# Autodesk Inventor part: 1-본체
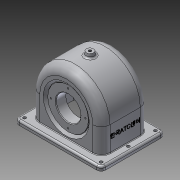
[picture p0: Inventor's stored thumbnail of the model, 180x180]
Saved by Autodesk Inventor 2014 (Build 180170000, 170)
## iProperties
Created: 2015-09
Part Number: 1-본체
Material: 알루미늄 6061
Document SubType Name: Modeling
Designer: Administrator
Density: 2.71 g/cm^3
Appearance: 알루미늄 - 평지
Mass: 809.5 g
Surface Area: 878.329 cm^2
Volume: 298.708 cm^3
Author: Administrator
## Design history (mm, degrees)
sketch "스케치1"
  geometry: L1 (57, 0)-(57, -47); L2 (57, -47)-(-57, -47); L3 (-57, -47)-(-57, 0); L4 (57, 0)-(-57, 0); A1 r 57 centre (0, 0) between (57, 0) and (-57, 0); 1 further point
  constraints: 8 end point, 2 perpendicular, 2 point on circle, 2 tangent, 1 centre point, 1 coincident, 1 vertical
  dimensions: "d3" = 57 radius of A1; "d4" = 104 dimension on A1 L2
extrude "돌출1" new body sketch "스케치1" distance "d5" = 77; taper "d6" = 0 deg
sketch "스케치2"
  geometry: L1 (-13, -13.5)-(127, -13.5); L2 (127, -13.5)-(127, 90.5); L3 (127, 90.5)-(-13, 90.5); L4 (-13, 90.5)-(-13, -13.5); L5 (0, 0)-(0, 77) reference; L6 (114, 0)-(0, 0) reference; 5 further points
  constraints: 8 end point, 4 midpoint, 2 parallel, 1 horizontal, 1 horizontal alignment, 1 perpendicular, 1 vertical alignment
  dimensions: "d7" = 140 distance of L2.end L3.end; "d8" = 104 distance of L3.end L1.start
extrude "돌출2" join sketch "스케치2" distance "d9" = 7; taper "d10" = 0 deg
fillet "모깎기1" dims "d11" = 14
feature "쉘1" dims "d12" = 5, "d103" = 7
sketch "스케치3"
  geometry: C1 r 31 at (0, 0); 1 further point
  constraints: 1 centre point, 1 coincident
  dimensions: "d13" = 62 diameter of C1
extrude "돌출3" join sketch "스케치3" distance "d14" = 10; taper "d15" = 0 deg
sketch "스케치4"
  geometry: L1 (5, 39.747)-(19, 28); L2 (19, 28)-(19, 0); L3 (19, 0)-(5, 0); L4 (5, 0)-(5, 39.747); L5 (5, 0)-(5, 43) reference; 1 further point
  constraints: 8 end point, 2 perpendicular, 1 collinear, 1 point on line, 1 vertical
  dimensions: "d16" = 28 distance of L1.end L2.end; "d17" = 50 deg angle of L2 L1; "d18" = 14 distance of L2.end L3.end
revolve "회전1" sketch "스케치4" stored, may be unused: angle "d19" = 90 deg
sketch "스케치7"
  geometry: L1 (5, 39.747)-(19, 28) reference; L2 (0, 37.416)-(5.263, 33); L3 (0, 0)-(0, 43) reference; L4 (3, 0)-(3, 33); L5 (3, 33)-(5.263, 33); L6 (3, 0)-(0, 0)
  constraints: 8 end point, 2 parallel, 1 horizontal, 1 perpendicular, 1 point on line
  dimensions: "d21" = 5 distance between parallel lines of L2 L1; "d22" = 3 distance between parallel lines of L4 L3; "d23" = 33 distance of L4.start L4.end
revolve "회전2" sketch "스케치7" stored, may be unused: angle "d25" = 90 deg
hole "구멍1" diameter "d28" = 40; stored, may be unused: countersink angle "d32" = 90 deg, drill point angle "d34" = 0 deg; dims "d26" = 10, "d27" = 10, "d29" = 6, "d30" = 4, "d31" = 2, "d33" = 8
node "작업 평면1"
sketch "스케치8"
  geometry: L1 (140, 104)-(140, 0) reference; L2 (0, 104)-(140, 104) reference; C1 r 6 at (70, 52); 2 further points
  constraints: 1 centre point, 1 horizontal alignment, 1 midpoint, 1 vertical alignment
  dimensions: "d37" = 12 diameter of C1
extrude "돌출4" join sketch "스케치8" stored distance "d38" = 5; taper "d39" = 10 deg
fillet "모깎기2" dims "d40" = 7
fillet "모깎기3" dims "d41" = 3
sketch "스케치9"
  geometry: L1 (0, 0)-(0, 28)
  constraints: 2 end point, 1 vertical
  dimensions: "d42" = 28 distance of L1.start L1.end
hole "구멍2" sketch "스케치9" at (0, 28) diameter "d43" = 2.459; stored, may be unused: countersink angle "d47" = 90 deg, drill point angle "d49" = 118 deg; dims "d44" = 7, "d45" = 4, "d46" = 2, "d48" = 9
sketch "스케치10"
  geometry: L1 (0, 0)-(0, -24)
  constraints: 2 end point, 1 vertical
  dimensions: "d53" = 24 distance of L1.start L1.end
hole "구멍3" sketch "스케치10" at (0, -24) diameter "d54" = 2.459; stored, may be unused: countersink angle "d58" = 90 deg, drill point angle "d60" = 118 deg; dims "d55" = 6, "d56" = 4, "d57" = 2, "d59" = 8
hole "구멍4" diameter "d66" = 4.459; stored, may be unused: countersink angle "d70" = 90 deg, drill point angle "d72" = 118 deg; dims "d67" = 20, "d68" = 4, "d69" = 2, "d71" = 8, "d73" = 10, "d74" = 10
fillet "모깎기4" dims "d75" = 0.5
fillet "모깎기5" dims "d76" = 1
fillet "모깎기6" dims "d77" = 3
chamfer "모따기1" distance "d78" = 1; stored, may be unused: second distance "d79" = 2, angle "d80" = 45 deg
sketch "스케치11"
  geometry: L1 (-119, 82.5)-(5, 82.5); L2 (5, 82.5)-(5, -5.5); L3 (5, -5.5)-(-119, -5.5); L4 (-119, -5.5)-(-119, 82.5); L5 (-127, 83.5)-(-127, -6.5) reference; L6 (6, 90.5)-(-120, 90.5) reference; 3 further points
  constraints: 8 end point, 2 midpoint, 2 parallel, 1 horizontal, 1 perpendicular
  dimensions: "d81" = 124 distance of L1.start L1.end; "d82" = 88 distance of L1.end L2.end; "d83" = 8 distance between parallel lines of L4 L5; "d84" = 8 distance between parallel lines of L6 L1; "d102" = 44 distance of L2.end point (5, 38.5) (derived)
hole "구멍5" sketch "스케치11" at (5, -5.5) diameter "d85" = 5; stored, may be unused: countersink angle "d89" = 90 deg, drill point angle "d91" = 0 deg; dims "d86" = 6, "d87" = 4, "d88" = 2, "d90" = 8
sketch "스케치12"
  geometry: L1 (13.398, 22.271)-(13.398, 26.729); L2 (13.398, 26.729)-(20.602, 26.729); L3 (20.602, 26.729)-(20.602, 22.271); L4 (20.602, 22.271)-(13.398, 22.271); L5 (47, 69.5)-(47, -20.5) reference; L6 (43, -20.5)-(43, 69.5) reference; L7 (40, 69.5)-(40, -20.5) reference; 4 further points
  constraints: 3 midpoint, 1 horizontal alignment, 2 other
  dimensions: "d99" = 30 distance from line of L5 point (17, 26.729)
feature "엠보싱1" sketch "스케치12" dims "d3" = 57, "d4" = 104, "d100" = 0.5, "d101" = 0
node "솔리드1"
pattern_circular "원형 패턴1" dims angle "d51" = 360 deg
pattern_circular "원형 패턴2" dims angle "d62" = 360 deg
pattern_linear "직사각형 패턴1" dims "d94" = 44 (= d102), "d97" = 124 (= d81)
other parameters: "d1" = 57, "d2" = 104, "d98" = 62 (derived)
